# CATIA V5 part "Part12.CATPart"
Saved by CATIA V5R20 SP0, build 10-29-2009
Part number: JT7.5x1.5
Revision: ANY
Definition: UNKNOWN
Nomenclature: JT7.5x1.5
Source: Unknown
Bounding box of the stored display mesh (mm): x -5.25 to 5.25, y -0.75 to 0.75, z -5.25 to 5.25
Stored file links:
  C:\Users\Utente\Desktop\IO LAVORO\3D X SITO CF\CUMSA\3D files SA\SA 120314\Part12.CATPart
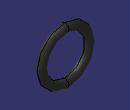
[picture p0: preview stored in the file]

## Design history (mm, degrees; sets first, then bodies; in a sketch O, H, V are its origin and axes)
Body1 "Revolución1" (main body)
  Solid1: solid without history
